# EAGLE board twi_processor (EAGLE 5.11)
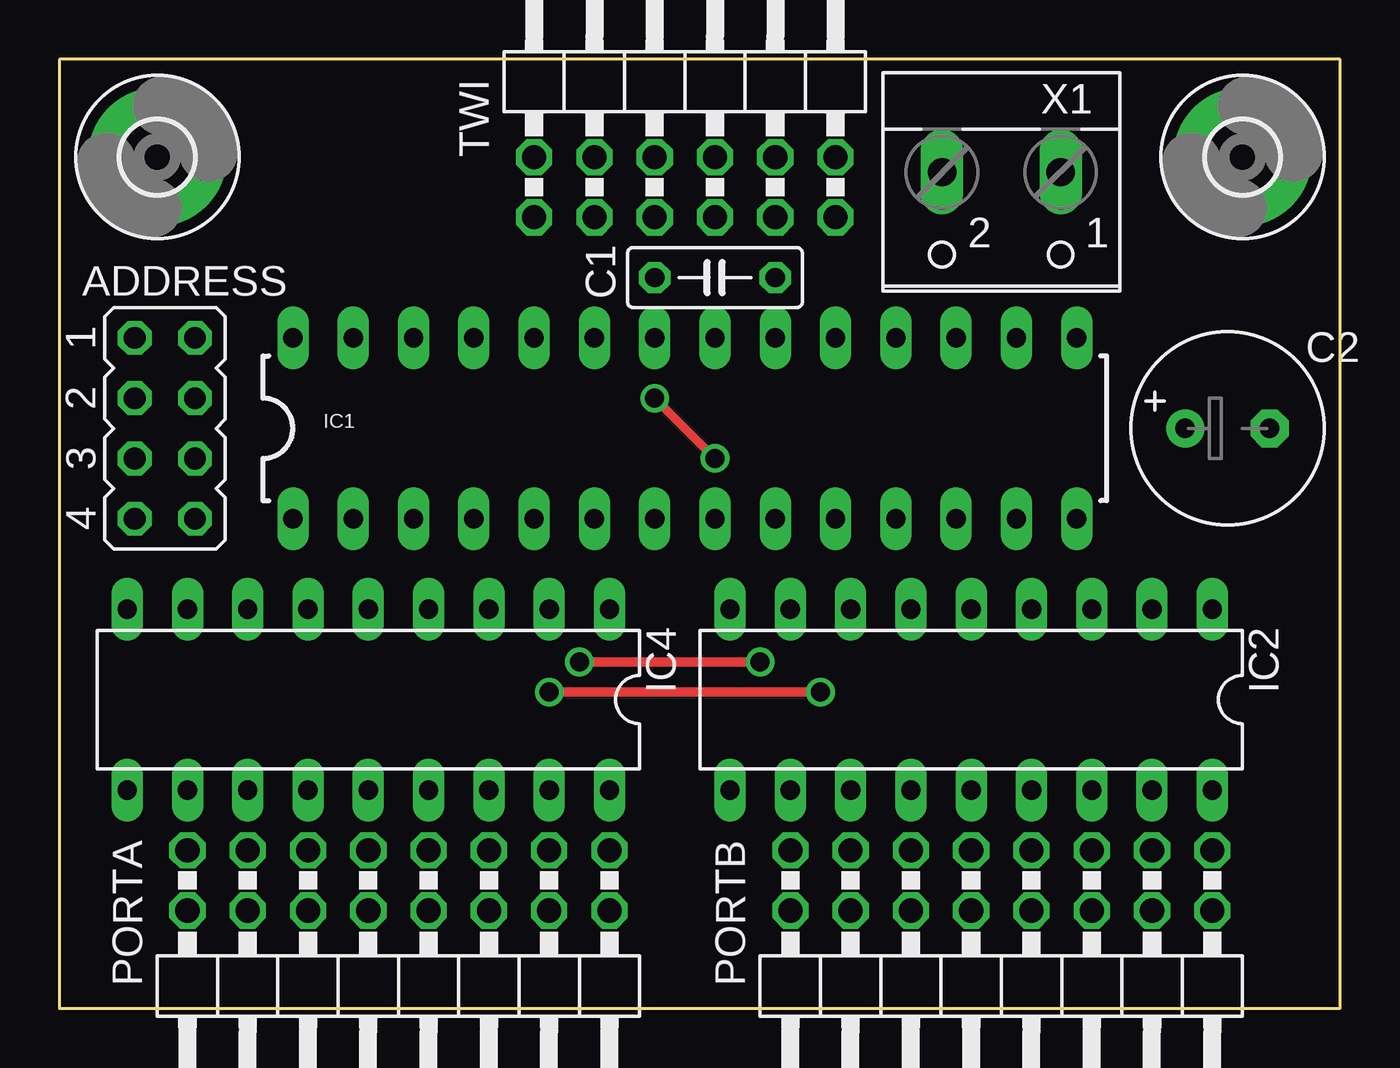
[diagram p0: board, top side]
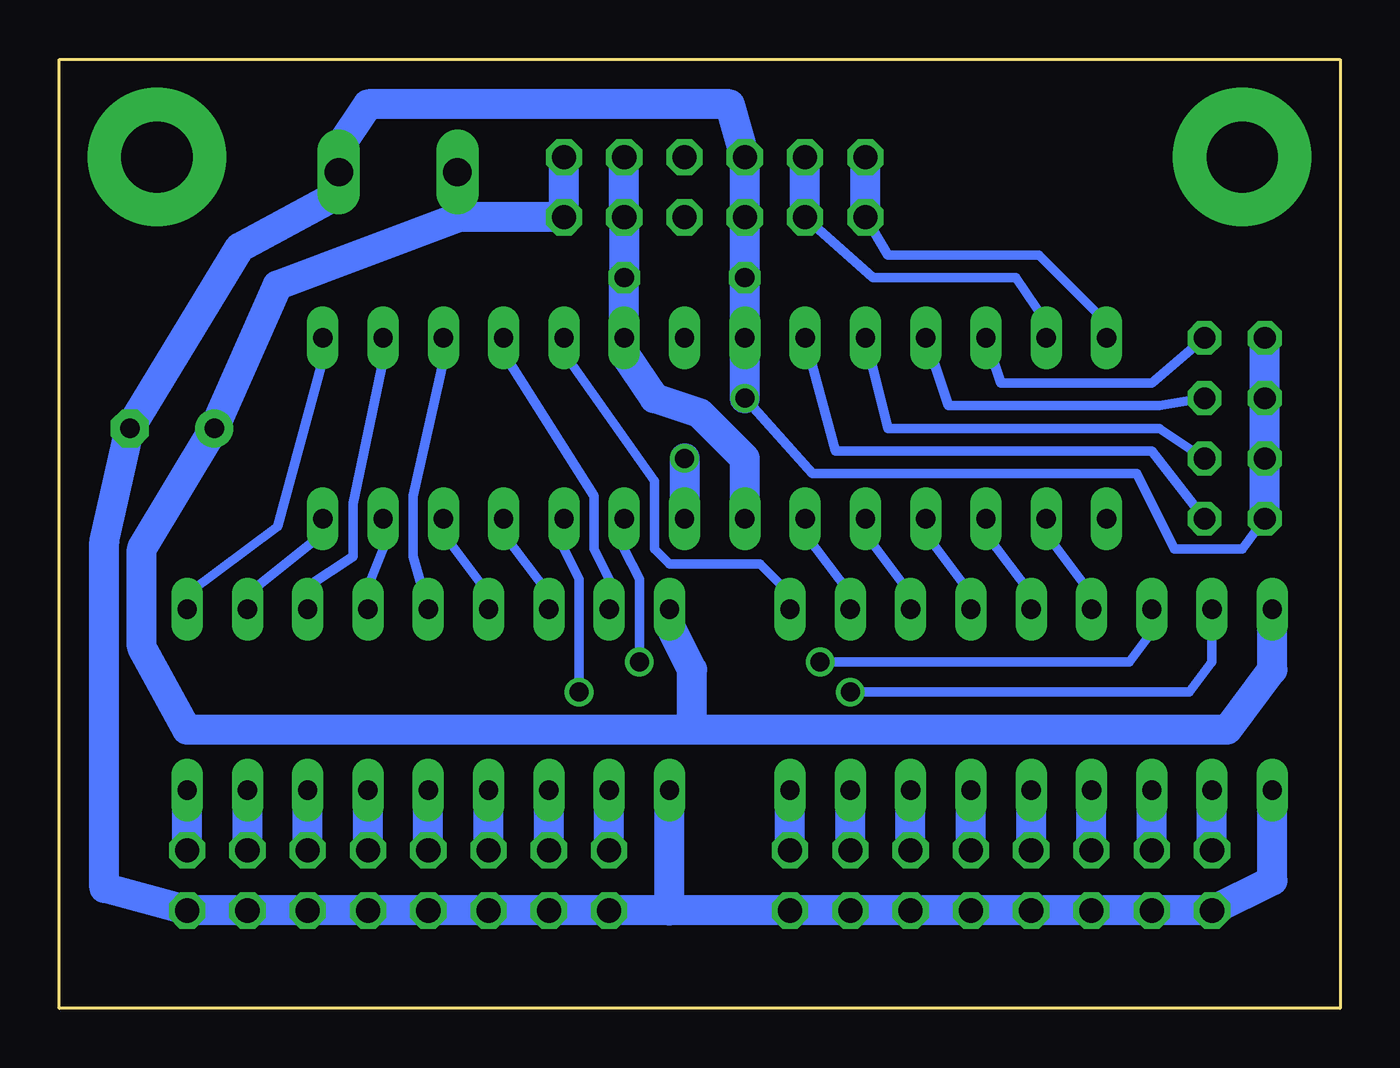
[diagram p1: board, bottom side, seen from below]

Size 53.96 x 40 mm. Coordinates in mm from the lower left corner, seen from the top.
Outline: 0,0 53.96,0 53.96,40 0,40 0,0
Copper layers (1*16): Top 0.035mm / dielectric 1.5mm / Bottom 0.035mm
Design rules "default": minimum track width 10mil, minimum drill 24mil, track to track 8mil, track to pad 8mil, pad to pad 8mil, via to via 8mil, smd to smd 8mil, copper to edge 40mil, drill to drill 8mil, minimum pad ring 10mil, minimum via ring 8mil, stop-mask expansion 4mil, vias tented up to drill 0mil, thermal gap 10mil

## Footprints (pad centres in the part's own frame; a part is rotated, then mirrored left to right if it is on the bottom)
JP4Q = drill 0.914 octagon: 1 -3.81,-1.27; 2 -3.81,1.27; 3 -1.27,-1.27; 4 -1.27,1.27; 5 1.27,-1.27; 6 1.27,1.27; 7 3.81,-1.27; 8 3.81,1.27
C050-025X075 = drill 0.813 octagon: 1 -2.54,0; 2 2.54,0
E3,5-8 = drill 0.813 pad 1.6 round: + -1.778,0 | drill 0.813 pad 1.6 octagon: - 1.778,0
3,0-PAD = drill 3 pad 5.842 round: B3,0 0,0
DIL28-3 = drill 0.813 long: 1 -16.51,-3.81; 2 -13.97,-3.81; 3 -11.43,-3.81; 4 -8.89,-3.81; 5 -6.35,-3.81; 6 -3.81,-3.81; 7 -1.27,-3.81; 8 1.27,-3.81; 9 3.81,-3.81; 10 6.35,-3.81; 11 8.89,-3.81; 12 11.43,-3.81; 13 13.97,-3.81; 14 16.51,-3.81; 15 16.51,3.81; 16 13.97,3.81; 17 11.43,3.81; 18 8.89,3.81; 19 6.35,3.81; 20 3.81,3.81; 21 1.27,3.81; 22 -1.27,3.81; 23 -3.81,3.81; 24 -6.35,3.81; 25 -8.89,3.81; 26 -11.43,3.81; 27 -13.97,3.81; 28 -16.51,3.81
DIL18 = drill 0.813 long: 1 -10.16,-3.81; 2 -7.62,-3.81; 3 -5.08,-3.81; 4 -2.54,-3.81; 5 0,-3.81; 6 2.54,-3.81; 7 5.08,-3.81; 8 7.62,-3.81; 9 10.16,-3.81; 10 10.16,3.81; 11 7.62,3.81; 12 5.08,3.81; 13 2.54,3.81; 14 0,3.81; 15 -2.54,3.81; 16 -5.08,3.81; 17 -7.62,3.81; 18 -10.16,3.81
2X08/90 = drill 1.016 octagon: 1 -8.89,-6.35; 2 -8.89,-3.81; 3 -6.35,-6.35; 4 -6.35,-3.81; 5 -3.81,-6.35; 6 -3.81,-3.81; 7 -1.27,-6.35; 8 -1.27,-3.81; 9 1.27,-6.35; 10 1.27,-3.81; 11 3.81,-6.35; 12 3.81,-3.81; 13 6.35,-6.35; 14 6.35,-3.81; 15 8.89,-6.35; 16 8.89,-3.81
2X06/90 = drill 1.016 octagon: 1 -6.35,-6.35; 2 -6.35,-3.81; 3 -3.81,-6.35; 4 -3.81,-3.81; 5 -1.27,-6.35; 6 -1.27,-3.81; 7 1.27,-6.35; 8 1.27,-3.81; 9 3.81,-6.35; 10 3.81,-3.81; 11 6.35,-6.35; 12 6.35,-3.81
W237-102 = drill 1.194 long: 1 -2.5,-1.27; 2 2.5,-1.27

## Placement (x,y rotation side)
ADDRESS  [JP4Q]  4.45,24.45 270 top
C1  100n  [C050-025X075]  27.62,30.8 180 top
C2  47µ  [E3,5-8]  49.21,24.45 0 top
H1  MOUNT-PAD-ROUND3.0  [3,0-PAD]  49.85,35.88 0 top
H2  MOUNT-PAD-ROUND3.0  [3,0-PAD]  4.13,35.88 0 top
IC1  AVR-MEGA8-PPTH  [DIL28-3]  26.35,24.45 0 top
IC2  UDN2981A  [DIL18]  38.42,13.02 180 top
IC4  UDN2981A  [DIL18]  13.02,13.02 180 top
PORTA  [2X08/90]  14.29,0.32 180 top
PORTB  [2X08/90]  39.69,0.32 180 top
TWI  [2X06/90]  26.35,39.69 0 top
X1  [W237-102]  39.69,33.97 180 top

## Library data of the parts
ADDRESS = jumper
C1 C2 = rcl
H1 H2 = holes
IC1 = SparkFun
IC2 IC4 = uln-udn
PORTA PORTB TWI = pinhead
X1 = con-wago-500; MPN: 237-102; OC_FARNELL: unknown; OC_NEWARK: 70K9898

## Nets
0: IC4.11 PORTA.15
1: IC4.12 PORTA.13
2: IC4.13 PORTA.11
3: IC4.14 PORTA.9
4: IC4.15 PORTA.7
5: IC4.16 PORTA.5
6: IC4.17 PORTA.3
7: IC4.18 PORTA.1
8: IC2.11 PORTB.15
9: IC2.12 PORTB.13
10: IC2.13 PORTB.11
11: IC2.14 PORTB.9
12: IC2.15 PORTB.7
13: IC2.16 PORTB.5
14: IC2.17 PORTB.3
15: IC2.18 PORTB.1
+5V: C1.1 IC1.7 IC1.20 TWI.9 TWI.10
+12V: C2.+ IC2.9 IC4.9 TWI.11 TWI.12 X1.2
GND: ADDRESS.1 ADDRESS.3 ADDRESS.5 ADDRESS.7 C1.2 C2.- IC1.8 IC1.22 IC2.10 IC4.10 PORTA.2 PORTA.4 PORTA.6 PORTA.8 PORTA.10 PORTA.12 PORTA.14 PORTA.16 PORTB.2 PORTB.4 PORTB.6 PORTB.8 PORTB.10 PORTB.12 PORTB.14 PORTB.16 TWI.5 TWI.6 X1.1
N$1: IC1.28 TWI.1 TWI.2
N$2: IC1.27 TWI.3 TWI.4
PB0: IC1.14 IC2.2
PB1: IC1.15 IC2.1
PB2: IC1.16 IC2.3
PB3: IC1.17 IC2.5
PB4: IC1.18 IC2.8
PB5: IC1.19 IC4.1
PB6: IC1.9 IC4.7
PB7: IC1.10 IC4.8
PC0: ADDRESS.8 IC1.23
PC1: ADDRESS.6 IC1.24
PC2: ADDRESS.4 IC1.25
PC3: ADDRESS.2 IC1.26
PD0: IC1.2 IC4.6
PD1: IC1.3 IC4.5
PD2: IC1.4 IC4.4
PD3: IC1.5 IC4.3
PD4: IC1.6 IC4.2
PD5: IC1.11 IC2.7
PD6: IC1.12 IC2.6
PD7: IC1.13 IC2.4

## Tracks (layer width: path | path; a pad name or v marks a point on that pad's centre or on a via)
0
  Bottom 1.27: PORTA.15 IC4.11
1
  Bottom 1.27: PORTA.13 IC4.12
2
  Bottom 1.27: PORTA.11 IC4.13
3
  Bottom 1.27: PORTA.9 IC4.14
4
  Bottom 1.27: PORTA.7 IC4.15
5
  Bottom 1.27: PORTA.5 IC4.16
6
  Bottom 1.27: PORTA.3 IC4.17
7
  Bottom 1.27: PORTA.1 IC4.18
8
  Bottom 1.27: PORTB.15 IC2.11
9
  Bottom 1.27: PORTB.13 IC2.12
10
  Bottom 1.27: PORTB.11 IC2.13
11
  Bottom 1.27: PORTB.9 IC2.14
12
  Bottom 1.27: PORTB.7 IC2.15
13
  Bottom 1.27: PORTB.5 IC2.16
14
  Bottom 1.27: PORTB.3 IC2.17
15
  Bottom 1.27: PORTB.1 IC2.18
+5V
  Bottom 1.27: IC1.7 25.08,23.18 26.99,25.08 28.89,25.72 30.16,27.62 IC1.20 C1.1 TWI.9 TWI.10
+12V
  Bottom 1.27: IC4.9 2.86,14.29 4.76,11.75 27.31,11.75 | 27.31,11.75 27.31,14.29 28.26,16.19 IC2.9 | 27.31,11.75 48.58,11.75 50.48,15.24 50.48,19.37 C2.+ 44.77,30.48 37.15,33.34 | 37.15,33.34 X1.2 | TWI.12 TWI.11 37.15,33.34
GND  (via drill 0.8)
  Top 0.406: v25.08,25.72 v27.62,23.18
  Bottom 0.406: ADDRESS.7 4.13,19.37 6.99,19.37 8.57,22.54 22.22,22.54 v25.08,25.72
  Bottom 1.27: v25.08,25.72 IC1.22 C1.2 TWI.5 TWI.6 25.72,38.1 40.96,38.1 42.23,36.19 X1.1 42.23,34.29 46.35,32.07 C2.- 52.07,19.68 52.07,5.08 PORTB.2 PORTB.4 PORTB.6 PORTB.8 PORTB.10 PORTB.12 PORTB.14 PORTB.16 28.26,4.13 | v27.62,23.18 IC1.8 | IC4.10 2.86,5.4 PORTA.16 PORTA.14 PORTA.12 PORTA.10 PORTA.8 PORTA.6 PORTA.4 PORTA.2 28.26,4.13 | 28.26,4.13 IC2.10 | ADDRESS.7 ADDRESS.5 ADDRESS.3 ADDRESS.1
N$1
  Bottom 0.406: TWI.1 19.05,31.75 12.7,31.75 9.84,28.89 IC1.28
  Bottom 1.27: TWI.1 TWI.2
N$2
  Bottom 0.406: TWI.3 19.68,30.8 13.65,30.8 12.38,28.89 IC1.27
  Bottom 1.27: TWI.3 TWI.4
PB0
  Bottom 0.406: IC1.14 42.86,20 46.04,17.46 IC2.2
PB1
  Bottom 0.406: IC1.15 42.86,27.31 44.77,20.32 48.58,17.46 IC2.1
PB2
  Bottom 0.406: IC1.16 40.32,27.31 41.59,21.27 41.59,19.05 43.5,17.78 IC2.3
PB3
  Bottom 0.406: IC1.17 37.78,27.31 39.05,21.59 39.05,19.05 IC2.5
PB4
  Bottom 0.406: IC1.18 35.24,27.62 31.43,21.59 31.43,19.37 30.8,18.1 IC2.8
PB5
  Bottom 0.406: IC1.19 32.7,27.62 28.89,22.22 28.89,19.37 28.26,18.73 24.45,18.73 23.18,17.46 IC4.1
PB6  (via drill 0.8)
  Top 0.406: v21.91,14.6 v29.53,14.6
  Bottom 0.406: IC1.9 30.16,19.37 29.53,18.1 v29.53,14.6 | v21.91,14.6 8.89,14.6 7.94,15.87 IC4.7
PB7  (via drill 0.8)
  Top 0.406: v20.64,13.34 v32.07,13.34
  Bottom 0.406: IC1.10 32.7,19.37 32.07,18.1 v32.07,13.34 | v20.64,13.34 6.35,13.34 5.4,14.6 IC4.8
PC0
  Bottom 0.406: IC1.23 21.27,23.49 7.94,23.49 ADDRESS.8
PC1
  Bottom 0.406: IC1.24 19.05,24.45 7.62,24.45 ADDRESS.6
PC2
  Bottom 0.406: IC1.25 16.51,25.4 7.62,25.4 ADDRESS.4
PC3
  Bottom 0.406: IC1.26 14.29,26.35 7.94,26.35 ADDRESS.2
PD0
  Bottom 0.406: IC1.2 12.38,20 10.48,17.46 IC4.6
PD1
  Bottom 0.406: IC1.3 14.92,20 13.02,17.46 IC4.5
PD2
  Bottom 0.406: IC1.4 17.46,20 15.56,17.46 IC4.4
PD3
  Bottom 0.406: IC1.5 20,20 18.1,17.46 IC4.3
PD4
  Bottom 0.406: IC1.6 22.54,20 20.64,17.46 IC4.2
PD5
  Bottom 0.406: IC1.11 35.24,20 33.34,17.46 IC2.7
PD6
  Bottom 0.406: IC1.12 37.78,20 35.88,17.46 IC2.6
PD7
  Bottom 0.406: IC2.4 40.96,17.78 40.32,19.37 IC1.13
